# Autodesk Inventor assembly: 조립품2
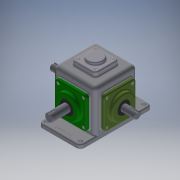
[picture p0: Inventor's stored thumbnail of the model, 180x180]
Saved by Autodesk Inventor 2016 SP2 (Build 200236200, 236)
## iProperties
Created: 2018-09
Part Number: 조립품2
Document SubType Name: Assembly
Designer: Administrator
Author: Administrator
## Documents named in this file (15)
- Z:\ATC마스터자격증시험\380907V1017 김영호\380907V1017\조립품2.iam
- Z:\ATC마스터자격증시험\380907V1017 김영호\380907V1017\본체.ipt
- Z:\ATC마스터자격증시험\380907V1017 김영호\380907V1017\메인커버.ipt
- Z:\ATC마스터자격증시험\380907V1017 김영호\380907V1017\서브커버.ipt
- Z:\ATC마스터자격증시험\380907V1017 김영호\380907V1017\베어링 6204.ipt
- Z:\ATC마스터자격증시험\380907V1017 김영호\380907V1017\베어링 6203.ipt
- Z:\ATC마스터자격증시험\380907V1017 김영호\380907V1017\메인축.ipt
- Z:\ATC마스터자격증시험\380907V1017 김영호\380907V1017\키 4x4.ipt
- Z:\ATC마스터자격증시험\380907V1017 김영호\380907V1017\메인베벨기어.ipt
- Z:\ATC마스터자격증시험\380907V1017 김영호\380907V1017\오일 실 20 35 8.ipt
- Z:\ATC마스터자격증시험\380907V1017 김영호\380907V1017\서브베벨기어.ipt
- Z:\ATC마스터자격증시험\380907V1017 김영호\380907V1017\오일 실 17 32 8.ipt
- Z:\ATC마스터자격증시험\380907V1017 김영호\380907V1017\상부커버.ipt
- Z:\ATC마스터자격증시험\380907V1017 김영호\380907V1017\서브축.ipt
- Z:\ATC마스터자격증시험\380907V1017 김영호\380907V1017\볼트 M4.ipt
## Named parameters: d3_d47 = 0, d4_d48 = 0, d5_d49 = 0, d7_d24 = 0, d8_d26 = 0, d9_d27 = 0, d10_d28 = 0, d11_d29 = 0, d12_d30 = 0, d13_d31 = 0, d14_d32 = 0, d15_d33 = 15 mm, d16_d34 = 15 mm, d17_d35 = 0, d18_d36 = 0, d19_d37 = 0, d20_d38 = 0, d21_d39 = 0, d22_d40 = 0, d23_d41 = 0, d24_d42 = 0, d25_d43 = 0, d26_d44 = 0, d27_d45 = 0, d28_d46 = 0
